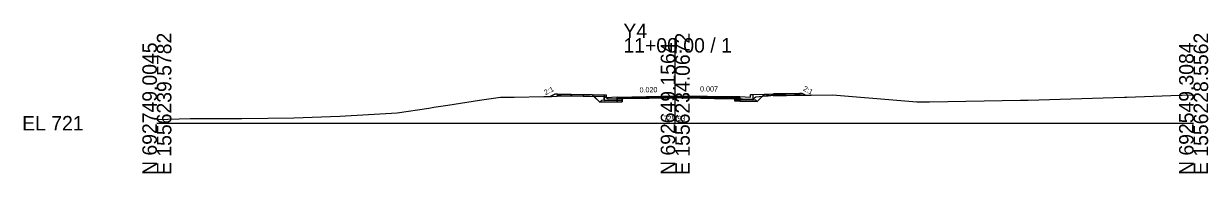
# Model space of a CAD drawing. Extents: x -26 to 203, y -10 to 1521.
# Drawn here: x -25.7 to 202.8, y 990.3 to 1019.2 of the extents above; entities that cross this region are included whole.
import ezdxf

# ---------------------------------------------------------------- set-up
doc = ezdxf.new("R2010")
doc.units = 0
for name, color, linetype in [('Exist CMT Pavement', 7, 'Continuous'), ('Exist Cross Section Cell', 7, 'Continuous'), ('Exist XS Center Line Elevation Label', 7, 'Continuous'), ('Exist XS Ground Line', 7, 'Continuous'), ('Prop CMT Conc Surface', 7, 'Continuous'), ('Prop CMT Concrete Structures', 7, 'Continuous'), ('Prop CMT Pvmt Course 1', 7, 'Continuous'), ('Prop CMT Pvmt Course 1 CG', 7, 'Continuous'), ('Prop CMT Pvmt Course 2', 7, 'Continuous'), ('Prop CMT Pvmt Course 3', 7, 'Continuous'), ('Prop CMT Pvmt Surface', 7, 'Continuous'), ('Prop CMT Slope Grass', 7, 'Continuous'), ('Prop CMT Subgrade Earthwork', 7, 'Continuous'), ('Prop XS Earthwork Shape', 7, 'Continuous'), ('Prop XS SE Text', 7, 'Continuous'), ('Prop XS Side Slope Text', 7, 'Continuous')]:
    doc.layers.add(name, color=color, linetype=linetype)

msp = doc.modelspace()

# ---------------------------------------------------------------- linework, layer by layer
at = {"layer": 'Exist CMT Pavement'}
for p, q in [((89.77, 1004.77), (100, 1004.93)), ((100, 1004.93), (100.94, 1004.94)), ((100.94, 1004.94), (101.55, 1004.93)), ((101.55, 1004.93), (101.55, 1004.93)), ((101.55, 1004.93), (102.16, 1004.93)), ((102.16, 1004.93), (107.57, 1004.8)), ((107.57, 1004.8), (111.49, 1004.71))]:
    msp.add_line(p, q, dxfattribs=at)
at = {"layer": 'Exist Cross Section Cell'}
for p, q in [((100, 1000), (100, 1016.45)), ((0, 1000), (100, 1000)), ((100, 1000), (200, 1000))]:
    msp.add_line(p, q, dxfattribs=at)
at = {"layer": 'Exist XS Ground Line'}
msp.add_lwpolyline([(0, 1000.73), (6.42, 1000.94), (16.42, 1000.91), (26.45, 1001.03), (35.27, 1001.38), (46.35, 1002.01), (52.48, 1002.9), (53.4, 1003.08), (56.16, 1003.51), (62.27, 1004.45), (66.32, 1005.04), (68.93, 1005.05), (74.68, 1005.19), (76.15, 1005.15), (78.36, 1005.29), (78.94, 1005.28), (83.06, 1005.21), (83.51, 1005.21), (86.41, 1005.14), (87.04, 1004.72), (88.87, 1004.75), (89.96, 1004.77), (100, 1004.93), (100.94, 1004.94), (102.16, 1004.93), (112.97, 1004.68), (114.91, 1004.64), (115.58, 1005.08), (117.62, 1005.29), (117.96, 1005.31), (119, 1005.39), (120.56, 1005.4), (123.98, 1005.4), (126.25, 1005.45), (130.33, 1005.48), (143.54, 1004.4), (146.62, 1004.16), (149.04, 1004.15), (166.64, 1004.44), (168.11, 1004.47), (186.68, 1005.04), (187.12, 1005.06), (195.63, 1005.33), (200, 1005.48)], dxfattribs=at)
at = {"layer": 'Prop CMT Conc Surface'}
for points in [[(82.27, 1005.51), (77.27, 1005.61)], [(114.49, 1005.06), (114.49, 1005.56), (114.99, 1005.56)], [(118.99, 1005.65), (123.99, 1005.75)], [(86.77, 1004.92), (86.77, 1005.42), (86.27, 1005.42)], [(88.77, 1005.04), (86.77, 1004.92)], [(112.49, 1005.18), (114.49, 1005.06)]]:
    msp.add_lwpolyline(points, dxfattribs=at)
at = {"layer": 'Prop CMT Concrete Structures'}
for points in [[(77.27, 1005.28), (77.27, 1005.61)], [(77.27, 1005.61), (82.27, 1005.51)], [(112.49, 1005.18), (114.49, 1005.06), (114.49, 1005.56), (114.99, 1005.56)], [(114.99, 1005.56), (114.99, 1004.55), (112.49, 1004.6)], [(123.99, 1005.75), (118.99, 1005.65)], [(118.99, 1005.65), (118.99, 1005.32)], [(123.99, 1005.42), (123.99, 1005.75)], [(82.27, 1005.18), (77.27, 1005.28)], [(82.27, 1005.51), (82.27, 1005.18)], [(88.77, 1005.04), (86.77, 1004.92), (86.77, 1005.42), (86.27, 1005.42)], [(86.27, 1005.42), (86.27, 1004.41), (88.77, 1004.46)], [(88.77, 1004.46), (88.77, 1005.04)], [(112.49, 1004.6), (112.49, 1005.18)], [(118.99, 1005.32), (123.99, 1005.42)]]:
    msp.add_lwpolyline(points, dxfattribs=at)
at = {"layer": 'Prop CMT Pvmt Course 1'}
for p, q in [((89.77, 1004.94), (100, 1005.14)), ((89.77, 1004.94), (89.77, 1004.81)), ((100, 1005.14), (111.49, 1005.06)), ((111.49, 1005.06), (111.49, 1004.94))]:
    msp.add_line(p, q, dxfattribs=at)
for points in [[(88.77, 1005.04), (88.77, 1004.79)], [(100, 1005.27), (100, 1005.02)], [(100, 1005.27), (112.49, 1005.18)], [(100, 1005.02), (100, 1005.27)], [(112.49, 1004.93), (100, 1005.02)], [(112.49, 1005.18), (112.49, 1004.93)]]:
    msp.add_lwpolyline(points, dxfattribs=at)
msp.add_lwpolyline([(100, 1005.02), (100, 1005.14), (100, 1005.14), (100, 1005.02)], close=True, dxfattribs=at)
at = {"layer": 'Prop CMT Pvmt Course 1 CG'}
for points in [[(88.77, 1004.46), (85.77, 1004.4), (85.43, 1004.06)], [(85.43, 1004.06), (88.77, 1004.13)], [(88.77, 1004.21), (88.77, 1004.46)], [(112.49, 1004.6), (115.49, 1004.54), (115.83, 1004.2)], [(112.49, 1004.35), (112.49, 1004.6)], [(115.83, 1004.2), (112.49, 1004.26)]]:
    msp.add_lwpolyline(points, dxfattribs=at)
at = {"layer": 'Prop CMT Pvmt Course 2'}
for p, q in [((88.77, 1004.79), (100, 1005.02)), ((89.77, 1004.81), (89.77, 1004.48)), ((111.49, 1004.6), (111.49, 1004.94))]:
    msp.add_line(p, q, dxfattribs=at)
for points in [[(88.77, 1004.79), (88.77, 1004.46)], [(100, 1005.02), (112.49, 1004.93)], [(112.49, 1004.6), (111.49, 1004.6)], [(112.49, 1004.93), (112.49, 1004.6)]]:
    msp.add_lwpolyline(points, dxfattribs=at)
at = {"layer": 'Prop CMT Pvmt Course 3'}
for p, q in [((88.77, 1004.46), (89.77, 1004.48)), ((89.77, 1004.48), (89.77, 1004.15)), ((111.49, 1004.6), (111.49, 1004.27))]:
    msp.add_line(p, q, dxfattribs=at)
for points in [[(88.77, 1004.46), (88.77, 1004.13)], [(111.49, 1004.6), (112.49, 1004.6)], [(112.49, 1004.6), (112.49, 1004.26)]]:
    msp.add_lwpolyline(points, dxfattribs=at)
at = {"layer": 'Prop CMT Pvmt Surface'}
msp.add_line((88.77, 1005.04), (100, 1005.27), dxfattribs=at)
msp.add_lwpolyline([(100, 1005.27), (112.49, 1005.18)], dxfattribs=at)
at = {"layer": 'Prop CMT Slope Grass'}
for p, q in [((75.86, 1005.16), (76.77, 1005.61)), ((125.14, 1005.42), (124.49, 1005.75))]:
    msp.add_line(p, q, dxfattribs=at)
for points in [[(86.27, 1005.42), (76.77, 1005.61)], [(114.99, 1005.56), (124.49, 1005.75)]]:
    msp.add_lwpolyline(points, dxfattribs=at)
at = {"layer": 'Prop CMT Subgrade Earthwork'}
for p, q in [((88.77, 1004.13), (89.77, 1004.15)), ((89.77, 1004.15), (89.77, 1004.77)), ((111.49, 1004.27), (111.49, 1004.71)), ((112.49, 1004.26), (111.49, 1004.27))]:
    msp.add_line(p, q, dxfattribs=at)
for points in [[(112.49, 1004.26), (115.83, 1004.2), (117.24, 1005.61)], [(88.77, 1004.13), (85.43, 1004.06), (84.02, 1005.47)]]:
    msp.add_lwpolyline(points, dxfattribs=at)
at = {"layer": 'Prop XS Earthwork Shape'}
for points in [[(77.97, 1005.27), (77.27, 1005.28), (77.27, 1005.61), (76.77, 1005.61), (75.86, 1005.16), (76.15, 1005.15)], [(117.24, 1005.61), (118.99, 1005.65), (118.99, 1005.39), (117.96, 1005.31), (117.62, 1005.29), (116.84, 1005.21)], [(123.04, 1005.4), (123.98, 1005.4), (125.14, 1005.42), (124.49, 1005.75), (123.99, 1005.75), (123.99, 1005.42)], [(77.97, 1005.27), (78.36, 1005.29), (78.94, 1005.28), (82.27, 1005.23), (82.27, 1005.18)], [(82.27, 1005.23), (83.06, 1005.21), (83.51, 1005.21), (84.3, 1005.19), (84.02, 1005.47), (82.27, 1005.51)], [(88.77, 1004.13), (89.77, 1004.15), (89.77, 1004.77), (88.87, 1004.75), (88.77, 1004.75), (88.77, 1004.46), (86.27, 1004.41), (86.27, 1005.14), (84.3, 1005.19), (85.43, 1004.06)], [(86.41, 1005.14), (87.04, 1004.72), (88.77, 1004.75), (88.77, 1004.46), (86.27, 1004.41), (86.27, 1005.14)], [(111.49, 1004.27), (111.49, 1004.71), (112.49, 1004.69), (112.49, 1004.6), (114.99, 1004.55), (114.99, 1004.69), (115.58, 1005.08), (116.84, 1005.21), (115.83, 1004.2), (112.49, 1004.26)], [(114.99, 1004.69), (114.99, 1004.55), (112.49, 1004.6), (112.49, 1004.69), (112.97, 1004.68), (114.91, 1004.64)], [(118.99, 1005.39), (119, 1005.39), (120.56, 1005.4), (123.04, 1005.4), (118.99, 1005.32)]]:
    msp.add_lwpolyline(points, close=True, dxfattribs=at)

# ---------------------------------------------------------------- texts
at = {"layer": 'Exist Cross Section Cell'}
for s, p in [('E 1556239.5782', (2.8, 990)), ('E 1556234.0672', (102.8, 990)), ('E 1556228.5562', (202.8, 990)), ('N 692749.0045', (0, 990)), ('N 692649.1564', (100, 990)), ('N 692549.3084', (200, 990))]:
    msp.add_text(s, height=2.8, rotation=90, dxfattribs=at).set_placement(p)
for s, p in [('Y4', (90, 1016.45)), ('11+00.00 / 1', (90, 1013.65)), ('EL 721', (-26, 998.6))]:
    msp.add_text(s, height=2.8, dxfattribs=at).set_placement(p)
at = {"layer": 'Exist XS Center Line Elevation Label'}
msp.add_text('725.93', height=1, dxfattribs=at).set_placement((97.74, 1000.43))
at = {"layer": 'Prop XS SE Text'}
for s, rotation, p in [('0.020', 0.843, (93.12, 1005.94)), ('0.007', 359.5989, (104.79, 1006.14))]:
    msp.add_text(s, height=1, rotation=rotation, dxfattribs=at).set_placement(p)
at = {"layer": 'Prop XS Side Slope Text'}
for rotation, p in [(26.5651, (74.99, 1005.41)), (333.4349, (124.56, 1006.37))]:
    msp.add_text('2:1', height=1, rotation=rotation, dxfattribs=at).set_placement(p)

doc.saveas('drawing.dxf')
